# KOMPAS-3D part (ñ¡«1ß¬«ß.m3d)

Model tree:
1. Эскиз:1
2. Операция выдавливания:1
     Расстояние 1 = 2; Расстояние 2 = 8.2
3. Эскиз:2
4. Операция выдавливания:2
     Расстояние 1 = 2; Расстояние 2 = 8.2
5. Скругление:1
     Радиус = 0.5
6. Скругление:2
     Радиус = 0.5

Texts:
  дно1скос
  Сплав АЛ8  ГОСТ 1583-93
